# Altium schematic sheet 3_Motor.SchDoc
size A4; SheetNumber: 3; SheetTotal: 4
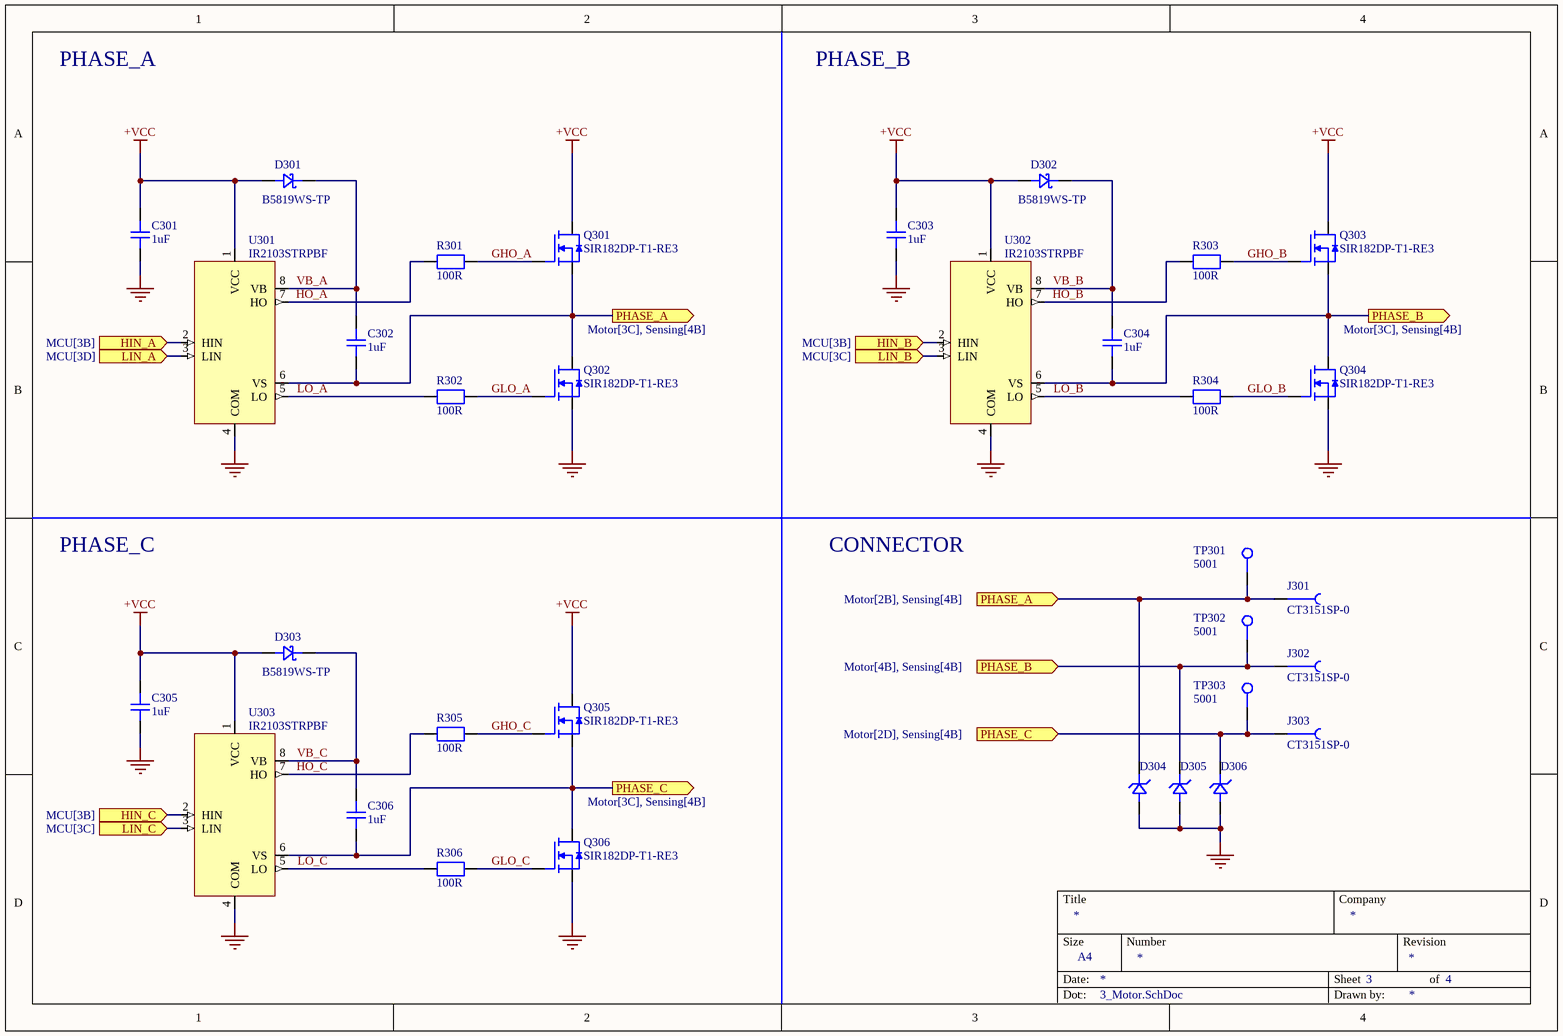
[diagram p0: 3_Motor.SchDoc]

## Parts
C301  value 1uF  [C_Yageo_CC_0603_A]  (hidden comment: CC0603KRX7R7BB105)
C302  value 1uF  [C_Yageo_CC_0603_A]  (hidden comment: CC0603KRX7R7BB105)
C303  value 1uF  [C_Yageo_CC_0603_A]  (hidden comment: CC0603KRX7R7BB105)
C304  value 1uF  [C_Yageo_CC_0603_A]  (hidden comment: CC0603KRX7R7BB105)
C305  value 1uF  [C_Yageo_CC_0603_A]  (hidden comment: CC0603KRX7R7BB105)
C306  value 1uF  [C_Yageo_CC_0603_A]  (hidden comment: CC0603KRX7R7BB105)
D301  B5819WS-TP  [D_Schottky_Micro_SOD-323]
D302  B5819WS-TP  [D_Schottky_Micro_SOD-323]
D303  B5819WS-TP  [D_Schottky_Micro_SOD-323]
D304  D5V0F1U2S9-7  [D_TVS_Uni_Diodes_SOD-923_B]  (value not drawn)
D305  D5V0F1U2S9-7  [D_TVS_Uni_Diodes_SOD-923_B]  (value not drawn)
D306  D5V0F1U2S9-7  [D_TVS_Uni_Diodes_SOD-923_B]  (value not drawn)
J301  CT3151SP-0  [J_CalTest_CT3151SP-0]
J302  CT3151SP-0  [J_CalTest_CT3151SP-0]
J303  CT3151SP-0  [J_CalTest_CT3151SP-0]
Q301  SIR182DP-T1-RE3  [Q_Vishay_PowerPACK-SO-8-Single]
Q302  SIR182DP-T1-RE3  [Q_Vishay_PowerPACK-SO-8-Single]
Q303  SIR182DP-T1-RE3  [Q_Vishay_PowerPACK-SO-8-Single]
Q304  SIR182DP-T1-RE3  [Q_Vishay_PowerPACK-SO-8-Single]
Q305  SIR182DP-T1-RE3  [Q_Vishay_PowerPACK-SO-8-Single]
Q306  SIR182DP-T1-RE3  [Q_Vishay_PowerPACK-SO-8-Single]
R301  value 100R  [R_Yageo_RCL_1206_A]  (hidden comment: RC1206FR-07100RL)
R302  value 100R  [R_Yageo_RCL_1206_A]  (hidden comment: RC1206FR-07100RL)
R303  value 100R  [R_Yageo_RCL_1206_A]  (hidden comment: RC1206FR-07100RL)
R304  value 100R  [R_Yageo_RCL_1206_A]  (hidden comment: RC1206FR-07100RL)
R305  value 100R  [R_Yageo_RCL_1206_A]  (hidden comment: RC1206FR-07100RL)
R306  value 100R  [R_Yageo_RCL_1206_A]  (hidden comment: RC1206FR-07100RL)
TP301  5001  [TP_Keystone_TH]
TP302  5001  [TP_Keystone_TH]
TP303  5001  [TP_Keystone_TH]
U301  IR2103STRPBF  [U_Infineon_8-SOIC_3.9mm]
U302  IR2103STRPBF  [U_Infineon_8-SOIC_3.9mm]
U303  IR2103STRPBF  [U_Infineon_8-SOIC_3.9mm]

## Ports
HIN_A (in, see MCU[3B]), HIN_B (in, see MCU[3B]), HIN_C (in, see MCU[3B]), LIN_A (in, see MCU[3D]), LIN_B (in, see MCU[3C]), LIN_C (in, see MCU[3C]), PHASE_A (in, see Motor[2B], Sensing[4B]), PHASE_A (out, see Motor[3C], Sensing[4B]), PHASE_B (in, see Motor[4B], Sensing[4B]), PHASE_B (out, see Motor[3C], Sensing[4B]), PHASE_C (in, see Motor[2D], Sensing[4B]), PHASE_C (out, see Motor[3C], Sensing[4B])

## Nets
+VCC: C301.2 C303.2 C305.2 D301.2 D302.2 D303.2 Q301.1(D) Q303.1(D) Q305.1(D) U301.1(VCC) U302.1(VCC) U303.1(VCC)
GND: C301.1 C303.1 C305.1 D304.2 D305.2 D306.2 Q302.3(S) Q304.3(S) Q306.3(S) U301.4(COM) U302.4(COM) U303.4(COM)
GHO_A: Q301.2(G) R301.2
GHO_B: Q303.2(G) R303.2
GHO_C: Q305.2(G) R305.2
GLO_A: Q302.2(G) R302.2
GLO_B: Q304.2(G) R304.2
GLO_C: Q306.2(G) R306.2
HIN_A: U301.2(HIN) ; port HIN_A
HIN_B: U302.2(HIN) ; port HIN_B
HIN_C: U303.2(HIN) ; port HIN_C
HO_A: R301.1 U301.7(HO)
HO_B: R303.1 U302.7(HO)
HO_C: R305.1 U303.7(HO)
LIN_A: U301.3(LIN) ; port LIN_A
LIN_B: U302.3(LIN) ; port LIN_B
LIN_C: U303.3(LIN) ; port LIN_C
LO_A: R302.1 U301.5(LO)
LO_B: R304.1 U302.5(LO)
LO_C: R306.1 U303.5(LO)
PHASE_A: C302.1 D304.1 J301.1 Q301.3(S) Q302.1(D) TP301.1 U301.6(VS) ; port PHASE_A
PHASE_B: C304.1 D305.1 J302.1 Q303.3(S) Q304.1(D) TP302.1 U302.6(VS) ; port PHASE_B
PHASE_C: C306.1 D306.1 J303.1 Q305.3(S) Q306.1(D) TP303.1 U303.6(VS) ; port PHASE_C
VB_A: C302.2 D301.1 U301.8(VB)
VB_B: C304.2 D302.1 U302.8(VB)
VB_C: C306.2 D303.1 U303.8(VB)

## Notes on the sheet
- PHASE_A
- PHASE_B
- PHASE_C
- CONNECTOR

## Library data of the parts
C301-C306 = CMP-001-00019-1: Multilayer Ceramic Capacitor, 1 uF, 16 V, ± 10%, X7R, 0603 [1608 Metric]; Voltage: 16V; Dissipation Factor: 5%
D301-D303 = CMP-004-00004-1: Rectifier Diode, Schottky, 1 Phase, 1 Element, 1A, 40V V(RRM), Silicon; Peak Non-Repetitive Surge Current: 10A; Value: 48pF; Max Reverse Leakage Current: 1mA; Forward Voltage: 900mV; Max Reverse Current: 7uA
D304-D306 = CMP-004-00003-1: Diode TVS Dual Uni-Dir 5.5V 250000W 2-Pin SOD-923 T/R; Max Power Dissipation: 250mW; ESD Protection: Yes; Max Reverse Leakage Current: 100nA; Capacitance: 0.5pF @ 1MHz; Max Surge Current: 1.5A; Diode Type: ZENER; Direction: Unidirectional; Breakdown Voltage: 6V; Clamping Voltage: 10V; Value: 5E-13F; Peak Pulse Power: 250kW; Number of Unidirectional Channels: 1
J301-J303 = CMP-002-00000-11: Conn 4mm Safety Banana Jack F 1 POS Solder RA Thru-Hole 1 Port Bag; pin to pad: 1>1+2+3+4; Gender: Female; Insulation: Mating End Insulated; Body Material: Nylon,Polyamide,PA66
Q301-Q306 = CMP-013-00000-2: TrenchFET Gen IV Power MOSFET N-Channel Single 60V VDS ±20V VGS 60A ID 8-Pin PowerPAK SOIC T/R; pin to pad: 1>5 2>4 3>1+2+3; Rds On Max: 2.8mR; Max Power Dissipation: 69.4W; Input Capacitance: 3.25nF
R301-R306 = CMP-009-00004-8: SMD Chip Resistor, 100 Ohm, ± 1%, 250 mW, 1206 [3216 Metric], Thick Film, General Purpose; Max Power Dissipation: 250mW; Voltage Rating (AC): 200V; Temperature Coefficient: 100ppm/°C
TP301-TP303 = CMP-000000-1: TEST POINT, PCB, THROUGH HOLE; Product R; Range: -; Connector Colour: Black; Mounting: Through Hole; Body Material: Bronze; Insulation: Insulated; Plating: Silver; Number of Ports: 1; Inside Diameter: 1.27mm; Hole Diameter: 1.6mm; Outside Diameter: 2.54mm
U301-U303 = CMP-024-00000-2: 600 V half-bridge gate driver IC with shoot through protection, SOIC 8N, RoHS; Number of Outputs: 2; Max Supply Voltage: 20V; Propagation Delay: 680ns; Fall Time: 60ns; Channel Type: Independent; Output Current: 360mA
